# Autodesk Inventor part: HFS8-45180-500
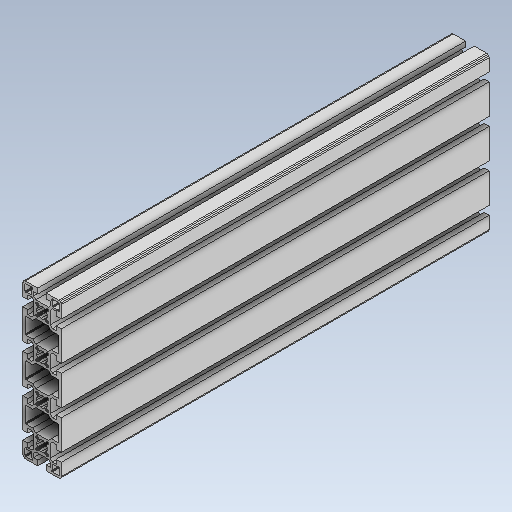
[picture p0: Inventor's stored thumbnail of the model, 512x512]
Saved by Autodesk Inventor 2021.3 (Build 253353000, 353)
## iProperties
Created: 2022-02
Part Number: HFS8-45180-500
Material: 一般
Document SubType Name: Modeling
Designer: kengo
Density: 1 g/cm^3
Appearance: 既定
Author: kengo
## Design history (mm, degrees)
feature "HFS8-45180-500"
node "ソリッド1"
